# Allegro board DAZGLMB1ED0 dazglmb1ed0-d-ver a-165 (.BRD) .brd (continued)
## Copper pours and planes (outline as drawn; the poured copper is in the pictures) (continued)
R_SPK+ on IN3 (solid shape): 24.79,12.39 24.79,9.49 24.53,9.24 23.77,9.24 23.52,9.49 23.52,12.32 23.79,12.6 24.58,12.6
R_SPK+ on IN3 (solid shape): 32.79,26.33 32.79,24.69 32.74,24.68 32.57,24.6 32.47,24.44 32.41,24.38 32.32,24.38 32.1,24.43 31.9,24.32 31.82,24.28 31.75,24.32 31.15,24.13 31.73,23.9 31.81,23.93 31.89,23.89 31.94,23.84 32,23.8 32,23.61 30.83,22.44 29.36,22.44 29.1,22.7 29.1,23.06 29.74,23.69 29.74,23.72 31.39,25.37 31.39,27.02 31.57,27.19 31.92,27.19
R_SPK- on TOP (solid shape): 24.07,12.26 24.07,11.88 23.87,11.68 23.82,11.68 23.06,10.91 23.06,7.71 22.93,7.59 22.3,7.59 22.04,7.84 22.04,10.79 23.16,11.91 23.16,12.21 23.31,12.36 23.97,12.36
R_SPK- on TOP (solid shape): 30.42,28.85 30.42,27.7 31.26,26.86 31.26,25.87 31.14,25.75 30.75,25.75 30.63,25.87 30.63,27.07 30.25,27.45 30.25,28.85 30.27,28.87 30.4,28.87
R_SPK- on IN3 (solid shape): 23.26,12.85 23.26,10.81 23.24,10.69 23.26,10.57 23.26,9.49 23.01,9.24 22.37,9.24 22.12,9.49 22.12,11.4 22.12,11.4 22.12,12.75 22.34,12.97 23.13,12.97
R_SPK- on IN3 (solid shape): 31.14,27.02 31.14,25.49 28.85,23.21 28.21,23.21 27.96,23.46 27.96,24.1 28.27,24.41 28.3,24.4 28.6,24.5 28.69,24.8 28.69,24.82 29.76,25.89 29.78,25.9 29.87,25.9 29.92,25.83 30.41,25.61 30.48,26.14 30.45,26.22 30.49,26.29 30.63,26.56 30.49,26.83 30.44,26.91 30.47,26.99 30.63,27.14 31.01,27.14
SWVGA1 on TOP (solid shape): 139.29,97.64 139.96,97.64 140.08,97.77 142.55,97.77 143.53,96.79 143.53,93.18 143.3,92.96 142.18,92.96 142.09,92.87 142.09,92.12 142.3,91.91 143.1,91.91 143.53,91.48 143.53,88.08 142.49,87.04 140.27,87.04 136.79,90.52 136.79,96.78 136.75,96.82 135.33,96.82 135.28,96.87 135.28,97.48 135.57,97.77 139.16,97.77
SWVGA2 on TOP (solid shape): 140.36,86.66 140.36,82.13 140.3,82.08 139.14,82.08 138.93,81.88 138.93,81.25 139.09,81.09 139.77,81.09 139.8,81.12 140.02,81.12 140.36,80.79 140.36,77.39 139.67,76.7 137.23,76.7 134.01,79.93 134.01,84.57 133.88,84.7 132.61,84.7 132.56,84.75 132.56,85.39 134.18,87.01 140,87.01
SWVGA3 on TOP (solid shape): 161.26,79.37 161.26,77.21 160.59,76.53 159.24,76.53 156.97,74.26 152.04,74.26 151.82,74.05 151.82,72.83 151.76,72.76 151.11,72.76 151.01,72.86 151.01,74.63 151,74.64 151,78.11 151.01,78.12 151.01,78.16 152.79,79.94 155.73,79.94 155.82,79.85 155.82,79.34 155.93,79.24 156.53,79.24 156.61,79.32 156.61,79.93 156.87,80.18 160.45,80.18
SWVGA4 on TOP (solid shape): 166.52,80.1 166.52,79.29 166.62,79.19 167.28,79.19 167.43,79.34 167.43,80.2 167.53,80.31 171.55,80.31 171.97,79.89 171.97,78.26 168.19,74.49 167.76,74.49 167.53,74.26 163.7,74.26 163.49,74.06 163.49,72.84 163.44,72.79 162.96,72.79 162.88,72.86 162.88,75.63 161.74,76.78 161.74,79.26 161.82,79.26 163.02,80.47 166.15,80.47
TERM9 on TOP (solid shape): 369.89,81.36 369.89,77.84 369.8,77.75 369.8,77.74 369.43,77.37 367.1,77.37 366.81,77.67 366.81,80.53 367.69,81.4 369.84,81.4
TERM9 on BOTTOM (solid shape): 369.43,79.68 369.43,66.84 369.23,66.64 367.2,66.64 367.13,66.72 367.13,70.14 367.27,70.5 367.13,70.86 367.13,79.86 367.39,80.13 368.98,80.13
TYPEC_VBUS on TOP (solid shape): 371.38,38.97 371.38,38.55 371.78,38.15 371.78,36.43 371.48,36.13 371.48,35.51 371.83,35.16 371.83,34.59 371.82,34.57 371.81,34.56 371.73,34.47 371.68,34.34 371.66,34.33 371.5,33.92 371.81,33.62 371.83,33.61 371.85,33.58 371.85,31.2 371.52,30.87 371.52,30.82 371.52,30.81 371.49,30.67 371.52,30.54 371.52,30.53 371.52,30.4 370.86,29.73 370.86,29.23 370.83,29.2 370.62,29.2 370.47,29.13 370.39,28.9 370.32,28.87 369.92,28.87 369.85,28.94 369.84,28.96 369.83,29.01 369.82,29.08 369.78,29.13 369.77,29.14 369.77,29.18 369.56,29.39 369.56,29.51 369.56,29.54 369.58,29.56 369.62,29.59 369.66,29.64 369.74,29.72 369.77,29.84 369.77,30.8 369.78,30.83 369.79,30.84 369.89,31.31 369.47,31.53 369.4,31.53 369.33,31.56 369.3,31.63 369.25,31.8 369.11,31.96 369.11,31.98 369.11,32.27 369.11,32.27 369.11,32.66 369.59,33.14 369.59,34.2 369.6,34.23 369.62,34.24 369.76,34.34 369.84,34.48 369.87,34.77 369.71,35 369.69,35.02 369.68,35.04 369.68,37.33 369.59,37.42 369.59,38.29 370.44,39.14 371.21,39.14
TYPEC_VBUS on IN3 (solid shape): outline of 1129 points within 370.2,36.4 381.66,45.56
USBPWR0 on TOP (solid shape): 26.03,84.85 26.03,83.23 27.3,81.96 27.3,81.09 27.29,80.99 27.3,80.89 27.3,80.56 26.99,80.26 24.33,80.26 24.18,80.41 24.18,84.73 24.4,84.95 25.93,84.95
USBPWR0 on BOTTOM (solid shape): 26.16,85.36 26.16,83.96 26.3,83.81 26.92,83.81 27.27,83.46 27.27,82.82 27.12,82.67 25.27,82.67 23.18,80.59 19.32,80.59 19.12,80.79 19.12,82.77 19.41,83.06 19.9,83.06 19.91,83.07 19.93,83.07 22.98,83.07 25.52,85.61 25.9,85.61
USBPWR2 on TOP (solid shape): 368.16,55.23 370.6,55.23 370.76,55.07 370.76,53.65 370.46,53.35 368.84,53.35 368.73,53.46 368.73,54.02 368.58,54.18 367.75,54.18 367.64,54.07 367.64,52.74 367.75,52.63 368.29,52.63 368.38,52.55 368.38,51.23 368.28,51.13 366.84,51.13 366.74,51.23 366.74,52.03 366.57,52.2 366.11,52.2 366.01,52.1 364.91,52.1 364.83,52.03 364.73,52.03 364.67,52.08 364.67,52.64 364.75,52.72 364.75,53.14 364.95,53.34 365.04,53.41 365.11,53.5 365.2,53.59 365.6,53.59 365.78,53.55 365.94,53.58 365.95,53.59 366.11,53.59 366.23,53.71 366.23,54.58 366.4,54.74 366.87,54.74 367.11,54.99 367.11,55.56 367.23,55.67 367.72,55.67
USBPWR2 on BOTTOM (solid shape): outline of 519 points within 367.72,53.41 378.11,59.8
USBPWR3 on TOP (solid shape): 20.39,67.4 20.39,64.41 20.2,64.22 19,64.22 19,64.21 18.97,64.18 16.89,64.18 16.56,64.51 16.56,66.11 16.78,66.34 18,66.34 18.54,66.87 18.54,67.5 18.69,67.66 20.14,67.66
USBPWR3 on TOP (solid shape): 14.75,45.88 17.05,45.88 17.95,44.97 17.95,43.4 17.94,43.36 17.9,43.35 14.6,43.35 14.06,43.89 14.06,45 13.77,45.29 13.12,45.29 13.04,45.37 13.03,45.38 12.47,45.73 11.85,45.49 11.67,44.89 12.02,44.37 12.02,44.37 12.38,44.01 12.4,43.97 12.38,43.94 12.13,43.69 12.12,43.68 11.92,43.56 11.77,43.37 11.75,43.36 11.72,43.35 10.21,43.35 9.98,43.58 9.98,46.2 10.29,46.51 14.12,46.51
USBPWR3 on BOTTOM (solid shape): 16.88,45.84 16.88,43.06 16.82,42.99 15.64,42.99 14.75,43.88 14.75,43.9 14.19,44.46 14.17,44.46 13.98,44.65 13.96,44.68 13.97,44.71 13.89,45.15 13.45,45.23 13.43,45.23 13.4,45.23 13,45.63 12.78,45.63 12.77,45.64 12.4,45.74 12.03,45.64 12.02,45.63 11.83,45.63 11.58,45.38 11.58,43.64 11.32,43.38 10.21,43.38 9.98,43.61 9.98,46.19 10.31,46.51 16.21,46.51
USBPWR3 on IN1 (solid shape): outline of 190 points within 9.34,42.84 16.91,46.73
USBPWR3 on IN2 (solid shape): outline of 2099 points within 8.78,38.65 18.16,66.67
VA on TOP (solid shape): 202.92,172.74 202.92,169.76 202.05,168.9 194.28,168.9 193.72,168.34 191.99,168.34 191.61,168.72 191.61,170.4 191.03,170.98 191.03,171.47 191.1,171.54 193.49,171.54 193.95,172 193.95,172.43 194.74,173.22 196.39,173.22 197.15,172.46 197.15,171.47 197.68,170.93 199.44,170.93 199.77,171.26 199.77,172.28 200.74,173.26 202.39,173.26
VA1 on TOP (solid shape): 208,170.18 208,165.42 206.31,163.74 192.47,163.74 191.8,164.41 191.8,165.92 192.88,167 192.88,167.63 193.14,167.89 193.7,167.89 194.53,168.72 202.25,168.72 203.17,169.64 203.17,170.04 203.41,170.29 207.89,170.29
VA2 on TOP (solid shape): 209.39,168.77 209.39,168.51 209.97,167.94 210.38,167.94 210.59,167.73 211.66,167.73 211.74,167.66 211.77,167.66 211.77,167.49 212.35,167.49 212.35,167.66 213.46,167.66 213.53,167.58 213.53,166.41 212.14,165.02 209.16,165.02 208.71,165.47 208.71,168.77 208.78,168.85 209.32,168.85
VL on BOTTOM (solid shape): 82.75,77.43 83.48,77.43 83.64,77.27 83.64,76.82 83.45,76.64 82.79,76.64 81.58,75.43 81.58,73.43 81.38,73.42 81.38,76.09 81.77,76.48 81.77,77.25 81.96,77.44 82.75,77.44
VREF_CA_DIMM0 on BOTTOM (solid shape): 235.78,54.66 236.66,54.66 236.77,54.54 236.77,51.75 236.68,51.66 235.05,51.66 234.84,51.86 234.84,53.79 234.74,53.89 234.74,54.63 235.08,54.96 235.48,54.96
VREF_CA_DIMM1 on BOTTOM (solid shape): 238.82,68.82 238.82,65.18 238.69,65.04 234.84,65.04 234.74,65.13 234.74,65.8 235.1,66.15 235.43,66.15 235.48,66.2 237.92,66.2 238.02,66.29 238.02,68.81 238.09,68.89 238.75,68.89
N19940934 on BOTTOM (solid shape): 76.7,75.1 76.7,72.78 76.25,72.33 76.09,72.33 75.74,71.98 75.41,71.98 75.35,72.04 75.35,72.35 75.84,72.84 75.84,75.02 76.07,75.25 76.55,75.25
N19940984 on BOTTOM (solid shape): 72.28,73.68 72.28,72.53 72.11,72.36 71.28,72.36 70.64,71.71 70.3,71.71 69.97,72.04 69.97,73.63 70.23,73.88 72.08,73.88
N19941188 on TOP (solid shape): 96.54,74.39 97.56,74.39 97.94,74.01 97.94,73.12 97.68,72.86 96.03,72.86 95.65,73.24 95.65,74.32 95.96,74.63 96.29,74.63
N19941230 on BOTTOM (solid shape): 87.27,74.26 87.27,73.32 87.82,72.77 87.82,72.16 87.64,71.97 86.38,71.97 86.13,72.23 86.13,74.39 86.25,74.51 87.02,74.51
N21715576 on BOTTOM (solid shape): 107.79,58.1 107.87,58.1 107.91,58.08 107.93,58.05 107.93,58.04 108.7,58.04 108.73,58 108.73,57.89 108.72,57.85 108.68,57.84 107.93,57.84 107.93,57.64 108.68,57.64 108.72,57.62 108.73,57.59 108.73,57.24 108.35,56.86 108.35,55.34 108.1,55.08 105.94,55.08 105.68,55.34 105.68,56.79 105.86,56.96 106.47,56.96 106.85,57.35 106.89,57.38 106.93,57.43 107.63,58.13 107.76,58.13
N21715610 on BOTTOM (solid shape): outline of 111 points within 110,59.44 113.3,62.96
N21715638 on BOTTOM (solid shape): 111.01,58.05 111.37,58.05 111.87,57.55 111.93,57.47 112.01,57.41 112.47,56.95 112.47,54.54 112.02,54.09 112.02,53.38 111.96,53.32 110.67,53.32 110.59,53.4 110.59,54.6 111.17,55.18 111.17,55.57 110.45,56.29 110.45,56.29 110.45,56.52 110.44,56.57 110.43,56.67 110.37,56.83 110.22,56.91 110.21,56.91 110,57.12 110,57.59 110.02,57.62 110.05,57.64 110.88,57.64 110.88,57.84 110.21,57.84 110.11,57.9 110.14,58.01 110.16,58.04 110.88,58.04 110.88,58.05 110.89,58.08 110.93,58.1 110.96,58.1
N21716526 on TOP (solid shape): 44.11,72.66 44.11,71.46 43.38,70.73 42.31,70.73 42.07,70.49 41.84,70.49 41.8,70.51 41.79,70.54 41.79,71.38 41.59,71.38 41.59,70.54 41.57,70.51 41.54,70.49 41.46,70.49 41.4,70.55 41.4,71.53 41.43,71.56 41.43,71.88 41.81,72.26 41.82,72.27 41.9,72.32 41.96,72.4 41.96,72.41 42.44,72.89 43.89,72.89
N21716528 on TOP (solid shape): 38.96,73.19 38.96,72.66 39.09,72.53 39.1,72.51 39.16,72.4 39.26,72.33 39.28,72.33 40,71.6 40,71.38 39.99,71.38 39.99,70.6 39.97,70.57 39.94,70.55 39.84,70.55 39.8,70.57 39.79,70.6 39.79,71.38 39.59,71.38 39.59,70.6 39.57,70.57 39.54,70.55 39.21,70.55 38.88,70.88 38.22,70.88 37.26,71.85 37.26,73.32 37.43,73.5 38.65,73.5
N21716560 on TOP (solid shape): 39.54,69.32 39.57,69.31 39.59,69.27 39.59,68.43 39.79,68.43 39.79,69.27 39.8,69.31 39.84,69.32 39.94,69.32 39.97,69.31 39.99,69.27 39.99,68.43 39.99,68.42 39.99,68.36 39.64,68.01 39.64,66.51 40.56,65.6 40.56,65.19 40.43,65.07 39.87,65.07 39.45,65.49 37.72,65.49 37.54,65.68 37.54,67.39 36.96,67.97 36.96,68.47 37.04,68.55 38.65,68.55 39.43,69.32
N21716588 on TOP (solid shape): 45.74,69.06 45.74,68.06 45.56,67.89 43.99,67.89 43.68,67.58 43.68,66.95 43.56,66.82 41.93,66.82 41.8,66.95 41.8,67.89 41.35,68.34 41.35,68.4 41.38,68.43 41.39,68.43 41.39,69.23 41.4,69.27 41.44,69.28 41.54,69.28 41.57,69.27 41.59,69.23 41.59,68.43 41.79,68.43 41.79,69.23 41.8,69.27 41.84,69.28 42.39,69.28 42.79,68.88 43.61,68.88 44.04,69.31 45.49,69.31
N23334357 on TOP (solid shape): 203.86,91.69 203.86,90.57 203.19,89.91 200.35,89.91 199.89,89.45 199.89,85.75 199.84,85.66 199.73,85.67 199.2,85.63 199.18,85.11 198.24,84.17 198.24,76.65 198.11,76.52 196.97,76.52 196.97,78.02 196.03,78.96 194.41,78.96 193.95,79.42 193.95,87.37 195.07,88.48 195.3,88.48 195.3,89.15 195.17,89.15 195.12,89.2 195.12,89.7 195.42,90.01 196.9,90.01 197.15,90.26 197.15,91.15 197.28,91.28 197.96,91.28 198.65,91.96 203.58,91.96
N25200237 on TOP (solid shape): 270.53,152.21 270.53,150.31 271.41,149.43 271.41,146.49 271.24,146.32 266.16,146.32 265.88,146.6 265.88,147.95 266.09,148.15 267.13,148.15 267.48,148.51 267.48,149.5 267.66,149.67 268.37,149.67 268.68,149.98 268.68,150.65 268.7,150.65 268.7,152.23 268.73,152.26 270.48,152.26
N25200251 on TOP (solid shape): 263.16,152.26 263.16,150.31 264.15,149.32 264.15,146.52 263.85,146.22 259,146.22 258.22,146.99 258.22,147.83 258.54,148.15 259.68,148.15 259.86,148.33 259.86,149.57 259.99,149.7 261.18,149.7 261.31,149.83 261.31,152.32 263.11,152.32
N25200989 on TOP (solid shape): 221.08,149.11 224.73,149.11 225.09,148.76 225.09,145.99 225.42,145.66 227.02,145.66 227.04,145.64 228.64,145.64 228.67,145.61 228.67,144.59 228.52,144.44 220.67,144.44 219.93,145.18 219.93,149.13 220.15,149.35 220.85,149.35
N25201029 on TOP (solid shape): 267.86,150.64 267.8,150.58 266.45,150.58 266.26,150.38 266.26,150.11 266.01,149.85 265.63,149.85 265.55,149.93 265.55,150.36 266.1,150.91 266.63,150.91 267.06,151.34 267.86,151.34
N25201083 on TOP (solid shape): 259.69,151.38 260.47,151.38 260.47,150.69 259.23,150.69 258.74,150.21 258.74,149.98 258.64,149.88 258.24,149.88 258.16,149.95 258.16,150.36 258.34,150.54 258.54,150.54 259.4,151.4 259.67,151.4
N25255306 on TOP (solid shape): 91.48,62.05 91.48,59.3 91.29,59.11 90.38,59.11 90.11,58.84 90.11,57.14 90.32,56.94 95.7,56.94 95.91,56.73 95.91,54.73 94.08,54.73 94.08,54.73 93.42,54.73 93.42,54.73 93.14,54.73 92.08,53.66 85.78,53.66 85.36,54.07 85.36,59.97 85.71,60.31 87.2,60.31 88.68,61.8 89.02,62.13 91.4,62.13
N25255465 on TOP (solid shape): 92.02,58.84 92.02,58.14 91.68,57.79 90.75,57.79 90.71,57.83 90.71,58.33 90.78,58.39 91.25,58.39 91.49,58.64 91.49,58.87 91.61,58.98 91.89,58.98
N25272069 on TOP (solid shape): 100.22,80.2 100.22,78.27 100.68,77.81 101.15,77.81 101.41,77.56 101.41,77.33 100.82,76.75 95.17,76.75 94.79,77.13 94.79,78.57 94.72,78.63 94.72,78.64 93.52,79.85 93.52,80.15 94.03,80.66 99.77,80.66
N25275939 on TOP (solid shape): 108.2,73.6 108.2,71.8 107.88,71.48 106.9,71.48 106.88,71.47 106.7,71.47 106.6,71.37 106.6,71.09 106.42,70.91 106.05,70.91 106.01,70.92 106,70.96 106,71.75 105.8,71.75 105.8,70.96 105.78,70.92 105.75,70.91 105.66,70.91 105.61,70.96 105.61,72.03 105.73,72.15 105.89,72.15 106.12,72.38 106.12,72.57 106.43,72.89 106.43,73.68 106.45,73.71 106.48,73.73 108.07,73.73
N25275943 on TOP (solid shape): 102.85,73.61 102.85,72.91 103.09,72.66 103.09,72.46 103.37,72.18 103.99,72.18 104.19,71.98 104.19,70.96 104.08,70.86 104.05,70.86 104.01,70.87 104,70.91 104,71.75 103.8,71.75 103.8,70.91 103.78,70.87 103.75,70.86 103.51,70.86 102.48,70.86 102.28,71.06 102.28,71.87 102.05,72.1 100.88,72.1 100.78,72.21 100.78,72.99 101.44,73.65 102.81,73.65
N25276025 on TOP (solid shape): 162.73,63.8 163.9,63.8 164.08,63.97 165.88,63.97 166.39,63.47 166.39,62.65 165.82,62.08 165.57,62.08 165.49,62.01 165.45,62.01 165.37,61.93 165.37,61.89 165.34,61.85 165.34,60.94 165.07,60.67 163.3,60.67 163.24,60.68 163.18,60.67 161.46,60.67 161.23,60.9 161.23,63.77 161.44,63.97 162.55,63.97
N25276032 on TOP (solid shape): 151.86,60.52 154.58,60.52 154.71,60.39 154.71,59.3 154.55,59.15 150.59,59.15 150.34,59.4 150.34,60.65 150.46,60.77 151.61,60.77
N25431044 on TOP (solid shape): 106.65,56.3 106.65,55.15 107.07,54.73 107.07,54.3 106.86,54.09 104.13,54.09 103.96,54.27 103.96,56.25 104.16,56.46 106.5,56.46
N25504898 on TOP (solid shape): 241.22,154.68 241.22,152.52 242.02,151.72 242.02,149.23 241.42,148.63 237.03,148.63 236.49,149.17 236.49,150.56 236.67,150.74 237.46,150.74 237.89,151.17 237.89,152.04 238.09,152.24 239.16,152.24 239.39,152.47 239.39,154.73 241.17,154.73
N25504904 on TOP (solid shape): 248.71,154.7 248.71,152.87 249.08,152.51 249.08,149.28 248.71,148.91 245.18,148.91 244.06,150.03 244.06,150.44 244.24,150.61 244.77,150.61 244.94,150.78 244.94,151.87 245.33,152.26 246.6,152.26 246.86,152.52 246.86,154.73 246.88,154.75 248.66,154.75
N25504978 on TOP (solid shape): 255.93,152.87 256.43,152.37 256.43,149.37 255.85,148.78 251.4,148.78 251.28,148.91 251.28,150.56 251.45,150.74 252.09,150.74 252.29,150.94 252.29,151.98 252.65,152.34 253.89,152.34 254.07,152.52 254.07,153.14 254.09,153.15 254.09,154.77 254.1,154.78 255.93,154.78
N30107216 on TOP (solid shape): 366.05,28.23 366.26,28.23 366.37,28.12 366.36,28.11 366.36,27.87 366.49,27.73 366.69,27.73 366.75,27.68 366.75,27.4 366.64,27.3 366.47,27.3 366.28,27.11 366.28,26.96 366.2,26.88 366.03,26.88 365.81,27.09 365.81,27.09 365.12,27.78 365.12,28.31 365.2,28.39 365.88,28.39
N30677370 on TOP (solid shape): 313.53,54.21 313.56,54.17 314.67,53.07 314.67,51.34 315.58,50.43 316.53,50.43 316.89,50.07 316.89,49.5 316.66,49.27 316.64,49.26 316.62,49.25 316.55,49.25 316.48,49.24 316.38,49.24 316.03,49.58 314.77,49.58 314.42,49.93 314.42,50.4 313.81,51.01 313.8,51.03 313.79,51.05 313.79,51.68 313.8,51.7 313.81,51.72 313.97,52.1 313.71,52.41 313.69,52.41 313.66,52.46 313.66,53.2 313.41,53.44 313.21,53.44 313.08,53.57 312.75,53.57 312.65,53.67 312.65,53.86 312.73,53.94 312.96,53.94 313.23,54.21 313.25,54.22 313.33,54.21 313.42,54.23 313.51,54.23
N30677370 on BOTTOM (solid shape): 318.61,49.58 318.61,49.39 318.49,49.27 317.96,49.27 317.88,49.18 317.88,49.08 317.82,48.92 317.83,48.75 317.83,48.74 317.83,48.71 317.72,48.61 317.05,48.61 316.97,48.65 316.96,48.74 316.8,49.19 316.32,49.16 316.21,49.14 316.15,49.23 316.15,49.67 316.25,49.78 318.41,49.78
N31399389 on TOP (solid shape): 174.16,71.23 174.16,70.27 173.96,70.06 173.96,69.46 173.9,69.4 173.9,68.05 173.88,68.04 173.64,68.04 173.62,68.06 173.62,69.31 173.25,69.31 173.25,68.05 173.24,68.02 173.21,68 173.2,68 173.17,68 172.95,68 172.93,68.01 172.92,68.02 172.89,68.05 172.89,69.79 173.35,70.25 173.35,71.19 173.52,71.36 173.52,71.49 173.6,71.57 173.82,71.57
N31810763 on BOTTOM (solid shape): 340.34,88.34 340.34,87.62 340.33,87.61 339.79,87.61 338.7,86.52 338.7,84.82 338.66,84.78 337.95,84.78 337.92,84.81 337.92,86.79 337.93,86.81 337.94,86.83 338.65,87.54 338.88,87.54 339.72,88.38 339.73,88.39 339.75,88.39 340.29,88.39
N31810778 on BOTTOM (solid shape): 352.41,94.39 352.41,93.65 352.01,93.26 351.02,93.26 351.02,93.26 350.22,93.26 350.07,93.41 350.07,94.31 350.21,94.45 352.34,94.45
N31996495 on TOP (solid shape): 44.67,49.58 44.71,49.57 44.72,49.53 44.72,49.32 44.09,48.68 44.09,47.73 44.05,47.65 43.97,47.62 43.53,47.13 44.17,46.94 44.2,46.95 44.24,46.93 44.55,46.63 44.55,45.46 44.19,45.1 43.45,45.1 42.95,45.61 42.95,46.12 42.36,46.7 41.3,46.7 40.61,47.39 40.61,48.12 41.15,48.67 42.5,48.67 43.42,49.58
N33701634 on TOP (solid shape): 258.58,170.79 258.59,170.68 258.59,168.88 258.21,168.49 257.45,168.49 257.2,168.24 256.56,168.24 256.43,168.37 256.43,169.72 257.46,169.72 257.46,169.66 257.47,169.6 257.49,169.55 257.51,169.5 257.54,169.45 257.58,169.41 257.62,169.37 257.67,169.34 257.72,169.32 257.77,169.3 257.83,169.3 257.88,169.3 257.94,169.3 257.99,169.32 258.04,169.34 258.09,169.37 258.13,169.41 258.17,169.45 258.2,169.5 258.23,169.55 258.24,169.6 258.25,169.66 258.25,169.72 258.24,169.77 258.23,169.83 258.2,169.88 258.17,169.93 258.13,169.97 258.09,170 258.04,170.04 257.99,170.06 257.94,170.07 257.88,170.08 257.83,170.08 257.77,170.07 257.72,170.06 257.67,170.04 257.62,170 257.58,169.97 257.54,169.93 257.51,169.88 257.49,169.83 257.47,169.77 257.46,169.72 256.43,169.72 256.43,170.27 257.07,170.91 258.47,170.91
N33701636 on TOP (solid shape): 257.2,166.72 257.2,165.45 255.8,164.05 254.53,164.05 254.15,163.67 253.64,163.67 253.51,163.8 253.51,165.83 254.53,166.84 257.07,166.84
N33857304 on TOP (solid shape): 27.15,29.3 27.15,29.02 26.28,28.16 25.93,28.16 25.8,28.29 25.8,29.15 26,29.35 27.1,29.35
N34874002 on BOTTOM (solid shape): 226.64,169.59 226.64,168.41 226.56,168.33 226.53,168.33 226.52,168.33 226.29,168.37 226.07,168.28 225.71,168.28 225.45,168.37 225.18,168.28 224.18,168.28 223.92,168.37 223.66,168.28 223.29,168.28 223.03,168.37 222.77,168.28 222.41,168.28 222.41,168.28 221.82,168.28 221.69,168.15 221.52,168.15 221.51,168.16 221.25,168.24 220.99,168.15 220.76,168.15 220.49,168.24 220.23,168.15 219.11,168.15 218.84,168.24 218.58,168.15 218.34,168.15 218.08,168.24 217.81,168.15 216.13,168.15 215.87,168.42 215.87,169.14 216.45,169.71 226.51,169.71
N35891500 on TOP (solid shape): 46.26,61.88 46.26,60.96 46.1,60.8 45.33,60.8 45.12,60.58 44.4,60.58 44.33,60.51 44.31,60.5 44.29,60.49 41.96,60.49 41.83,60.62 41.83,61.18 42.04,61.4 42.72,61.4 42.94,61.61 44.93,61.61 45.44,62.12 46.02,62.12
N36392478 on TOP (solid shape): 41.19,46.37 41.19,45.25 41.5,44.95 42.18,44.95 42.49,44.64 42.49,44.16 42.39,44.06 40.56,44.06 40.41,44.21 40.41,44.38 40.42,44.49 40.41,44.59 40.41,45.07 39.87,45.61 39.71,45.61 39.5,45.83 39.5,46.23 39.69,46.42 41.14,46.42
N37522594 on TOP (solid shape): 374.69,93.49 374.69,90.53 373.84,89.68 371.27,89.68 370.77,89.18 370.77,86.86 370.69,86.79 369.86,86.79 369.48,87.16 369.48,89.25 368.89,89.85 368.89,92.1 369.3,92.51 372.74,92.51 373.01,92.77 373.01,93.66 373.32,93.97 374.21,93.97
N37522596 on TOP (solid shape): 365.28,93.61 365.28,89.7 366.41,88.57 366.41,87.94 366.32,87.85 365.89,87.85 365.87,87.87 365.87,88.54 365.75,88.54 365.46,88.83 363.11,88.83 361.95,89.99 361.29,89.99 360.9,89.59 360.9,89.27 360.78,89.15 359.84,89.15 359.43,89.55 359.43,91.14 358.4,92.17 358.4,93.35 358.84,93.78 359.5,93.78 360.42,92.86 362.01,92.86 362.91,93.76 362.91,93.77 363.29,94.15 364.74,94.15
N37550876 on TOP (solid shape): 357.21,90.36 357.21,89.45 356.95,89.19 356.7,89.45 356.7,90.15 356.35,90.49 356.08,90.49 355.78,90.19 354.81,90.19 354.79,90.16 354.7,90.11 354.6,90.09 354.01,90.09 353.37,90.72 353.37,91.08 353.73,91.08 354.22,90.59 354.5,90.59 354.6,90.69 355.57,90.69 355.65,90.78 355.65,90.84 355.68,90.84 355.68,91.28 355.77,91.39 355.91,91.43 356.13,91.43
N37550892 on TOP (solid shape): 353.44,88.23 353.46,88.22 353.48,88.21 353.84,88 354.2,88.21 354.22,88.22 354.25,88.23 355.32,88.23 355.34,88.23 355.35,88.22 355.65,88.1 355.94,88.22 355.95,88.23 355.97,88.23 358.63,88.23 358.76,88.11 358.76,87.44 358.68,87.37 358.19,87.37 357.73,86.91 357.73,86.33 357.35,85.94 350.92,85.94 350.54,86.33 350.54,87.53 351.04,88.03 351.97,88.03 352.17,88.23
N37551635 on TOP (solid shape): 355.83,94.47 355.93,94.4 355.9,94.29 356.15,93.59 356.41,94.29 356.38,94.4 356.47,94.47 357.93,94.47 357.97,94.45 357.98,94.42 357.98,92.8 357.8,92.63 354.24,92.63 354.1,92.76 354.1,93.22 354.14,93.27 354.17,93.34 354.34,93.51 354.86,93.51 355.01,93.67 355.01,94.17 355.3,94.47
N37576565 on BOTTOM (solid shape): 119.93,88.33 120.8,88.33 121,88.13 121,87.47 120.8,87.27 119.17,87.27 118.89,87.55 118.89,88.64 119.07,88.82 119.45,88.82
N37576617 on BOTTOM (solid shape): 110.1,88.08 110.1,85.56 109.98,85.44 109.09,85.44 108.86,85.67 108.86,88.21 109.04,88.38 109.8,88.38
N45490354 on TOP (solid shape): 107.28,62.91 108.07,62.91 108.63,62.35 108.63,61.69 108.55,61.61 106.65,61.61 105.43,62.83 105.43,63.54 105.48,63.59 106.6,63.59
N46383446 on BOTTOM (solid shape): 378.55,11.43 379.16,11.43 379.18,11.41 379.18,10.67 379.16,10.65 378.46,10.65 378.32,10.78 378.32,10.8 377.94,11.16 377.54,10.82 377.54,10.81 377.16,10.43 376.51,10.43 376.46,10.48 376.46,11.25 376.26,11.25 376.26,10.49 376.21,10.44 376.1,10.44 376.07,10.48 376.07,11.5 376.14,11.57 376.38,11.57 376.62,11.48 376.86,11.56 376.87,11.57 377.01,11.57 377.16,11.42 377.35,11.41 377.51,11.42 377.63,11.53 377.68,11.59 377.82,11.73 378.25,11.73
N46384360 on BOTTOM (solid shape): 373.32,11.54 374.54,11.54 374.66,11.43 374.66,11.25 374.66,11.25 374.66,10.51 374.59,10.44 374.51,10.44 374.46,10.5 374.46,11.25 374.45,11.25 374.26,11.25 374.26,11.25 374.26,10.51 374.19,10.44 373.68,10.44 373.03,11.09 371.6,11.09 371.44,11.24 371.44,11.62 371.57,11.75 372.08,11.75 372.3,11.97 372.89,11.97
N46825921 on BOTTOM (solid shape): 125.89,59.03 126.2,59.03 126.33,58.89 127.53,58.89 127.68,58.74 127.68,57.93 127.45,57.7 126.11,57.7 125.47,58.34 124.76,58.34 124.71,58.39 124.71,58.59 124.75,58.63 125.55,58.63 125.55,58.83 124.71,58.83 124.71,58.97 124.77,59.03 125.55,59.03 125.55,59.05 125.87,59.05

Small or netless copper shapes (teardrops, artwork), in the pictures only: 42 on TOP, 140 on BOTTOM, 15 on IN1, 92 on IN2, 59 on IN3, 3 on IN5

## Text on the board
Ref Des/Silkscreen Bottom: DAZGLMB1EC0 REV:C
User.Comments: 28.0x49.0 | 35.0x51.0 | 24.0x67.0 | 20.0x69.0 | 24.0x87.0 | 35.0x91.0 | 39.0x98.0 | 30.0x32.0
Ref Des/Silkscreen Top: DAZGLMB1ED0 | REV:D | MODEL:ZGL
IN2: fbvddq_mem | nvvdd
IN3: +3v | fbvddq_mem | nvvdd | +vccio | +vcc_core | +vcc_gt
SGND4: SGND4 | 9
SGND5: SGD5 | 11
SGND6: SGND6 | 13
User.13: GND | +5V_S5 | ADOGND | +3V | +VIN | FBVDDQ_MEM | NVVDD | +1.2VSUS | +VCCIO | +VCC_SA | +5VPCU | +VCC_CORE | +VCC_GT
User.24: U3 | GPU FAN LED | CPU FAN LED
User.28: ADOGND | GND
User.29: ADOGND | GND
User.30: ADOGND | GND
User.31: ADOGND | GND
User.32: ADOGND | GND
User.33: ADOGND | GND
User.45: PT_TOP | PT_BOT | FIGURE | TYPE | Oblong | Circle | SIZE | 51.0x24.0 | 55.0x31.0 | 67.0x39.0 | 71.0x35.0 | 75.0x24.0 | 79.0x28.0 | 83.0x31.0 | 83.0x35.0 | 102.0x28.0 | 152.0x112.0 | 8.0 | 10.0 | 14.0 | 20.0 | 22.0 | 28.0 | 31.0 | 35.0 | 39.0 | 59.0 | 118.0 | 126.0 | 150.0 | 162.0 | 177.0 | 30.0 | 32.0 | 38.0 | 43.0 | 47.0 | 55.0 | 63.0 | 67.0 | DRILL CHART: TOP to BOTTOM | ALL UNITS ARE IN MILS | PLATED | NON-PLATED | ROTATION | 90.000 | 0.000 | - | QTY | 2 | 12 | 6 | 4 | 1 | 59 | 2669 | 6937 | 40 | 1033 | 66 | 39 | 31 | 8 | 5 | 3 | 10873 | TOTAL HOLES:
